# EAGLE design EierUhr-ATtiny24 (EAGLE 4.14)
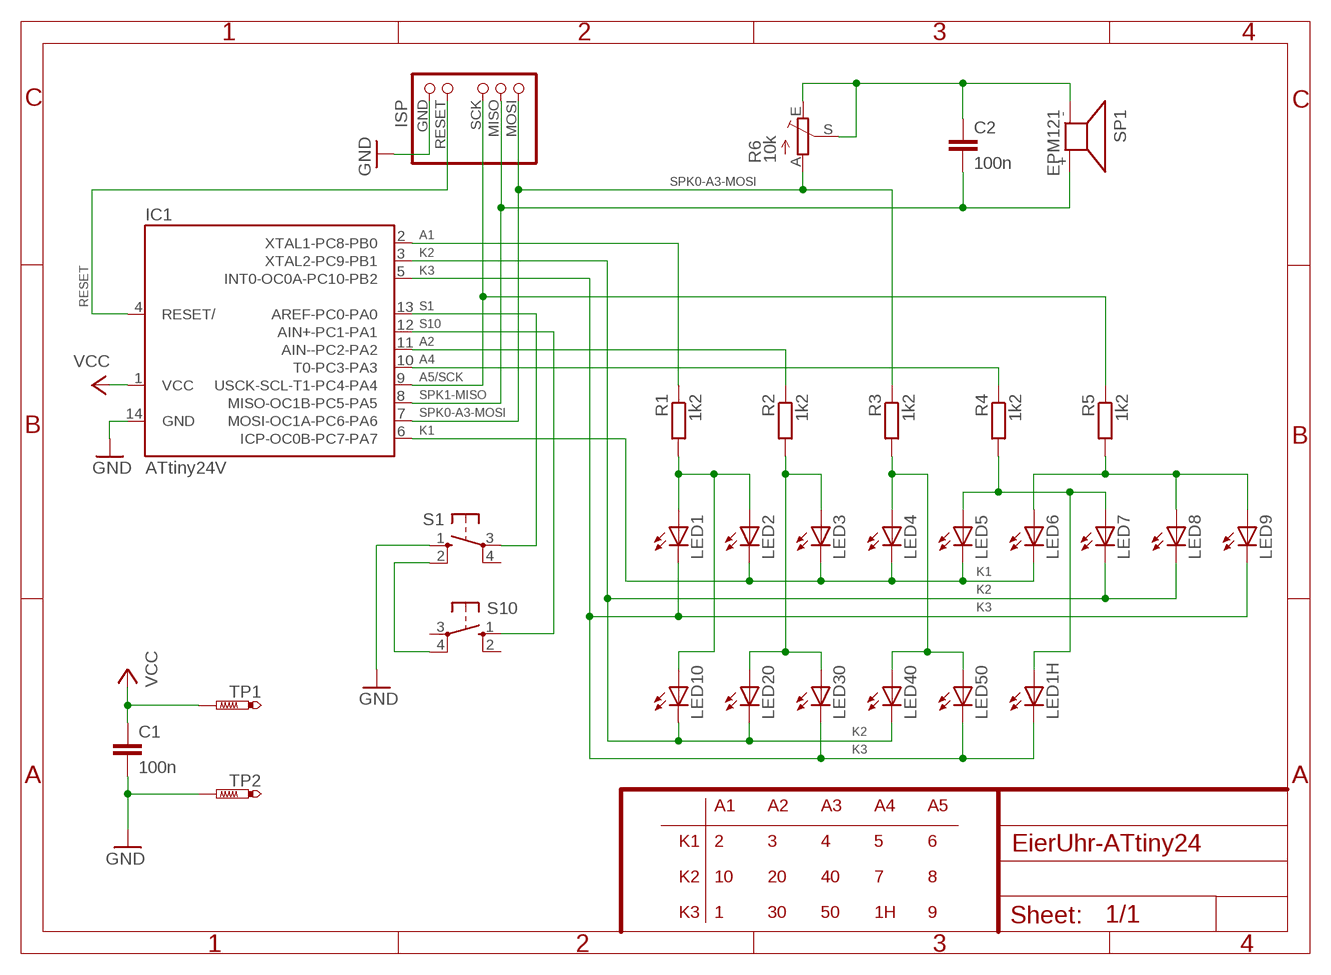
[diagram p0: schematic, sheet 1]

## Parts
C1  100n  C-EU050-024X044  [C050-024X044]
C2  100n  C-EU050-024X044  [C050-024X044]
IC1  ATtiny24V  ATTINY24P  [DIL14]
ISP  ISP-2  [PINHD6.ISP-2]
LED1  LED3MM  [LED3MM]
LED1H  LED3MM  [LED3MM]
LED2  LED3MM  [LED3MM]
LED3  LED3MM  [LED3MM]
LED4  LED3MM  [LED3MM]
LED5  LED3MM  [LED3MM]
LED6  LED3MM  [LED3MM]
LED7  LED3MM  [LED3MM]
LED8  LED3MM  [LED3MM]
LED9  LED3MM  [LED3MM]
LED10  LED3MM  [LED3MM]
LED20  LED3MM  [LED3MM]
LED30  LED3MM  [LED3MM]
LED40  LED3MM  [LED3MM]
LED50  LED3MM  [LED3MM]
R1  1k2  R-EU_0204/5  [0204/5]
R2  1k2  R-EU_0204/5  [0204/5]
R3  1k2  R-EU_0204/5  [0204/5]
R4  1k2  R-EU_0204/5  [0204/5]
R5  1k2  R-EU_0204/5  [0204/5]
R6  10k  TRIM_EU-S75H  [S75H]
S1  10-XX  [B3F-10XX]
S10  10-XX  [B3F-10XX]
SP1  EPM121  AL11P  [AL11P]
TP1  PTR1PAD1-13  [P1-13]
TP2  PTR1PAD1-13  [P1-13]

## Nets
A1: IC1.2(XTAL1-PC8-PB0) R1.1
A1.R: LED1.A LED2.A LED10.A R1.2
A2: IC1.11(AIN--PC2-PA2) R2.1
A2.R: LED3.A LED20.A LED30.A R2.2
A3.R: LED4.A LED40.A LED50.A R3.2
A4: IC1.10(T0-PC3-PA3) R4.1
A4.R: LED1H.A LED5.A LED7.A R4.2
A5.R: LED6.A LED8.A LED9.A R5.2
A5/SCK: IC1.9(USCK-SCL-T1-PC4-PA4) ISP.SCK R5.1
GND: C1.2 IC1.14(GND) ISP.GND S1.1(S) TP2.1(TP)
GND2: S1.2(S1) S10.4(P1)
K1: IC1.6(ICP-OC0B-PC7-PA7) LED2.K(C) LED3.K(C) LED4.K(C) LED5.K(C) LED6.K(C)
K2: IC1.3(XTAL2-PC9-PB1) LED7.K(C) LED8.K(C) LED10.K(C) LED20.K(C) LED40.K(C)
K3: IC1.5(INT0-OC0A-PC10-PB2) LED1.K(C) LED1H.K(C) LED9.K(C) LED30.K(C) LED50.K(C)
RESET: IC1.4(RESET/) ISP.RESET
S1: IC1.13(AREF-PC0-PA0) S1.3(P)
S10: IC1.12(AIN+-PC1-PA1) S10.1(S)
SPK: C2.1 R6.E R6.S SP1.-
SPK0-A3-MOSI: IC1.7(MOSI-OC1A-PC6-PA6) ISP.MOSI R3.1 R6.A
SPK1-MISO: C2.2 IC1.8(MISO-OC1B-PC5-PA5) ISP.MISO SP1.+
VCC: C1.1 IC1.1(VCC) TP1.1(TP)
Unconnected: S1.4(P1) S10.2(S1) S10.3(P)

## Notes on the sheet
- A1 | A2 | A3 | A4 | A5
- K1 | 2 | 3 | 4 | 5 | 6
- K2 | 10 | 20 | 40 | 7 | 8
- K3 | 1 | 30 | 50 | 1H | 9

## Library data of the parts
C1 C2 = rcl:C-EU: CAPACITOR, European symbol
IC1 = atmel-gjl:ATTINY24
ISP = eigene:ISP
LED1 LED1H LED2-LED10 LED20 LED30 LED40 LED50 = led:LED: LED
R1-R5 = rcl:R-EU_: RESISTOR, European symbol
R6 = pot:TRIM_EU-: POTENTIOMETER
S1 S10 = switch-omron:10-XX: OMRON SWITCH
SP1 = buzzer:AL11P: SPEAKER
TP1 TP2 = testpad:PTR1: TEST PIN

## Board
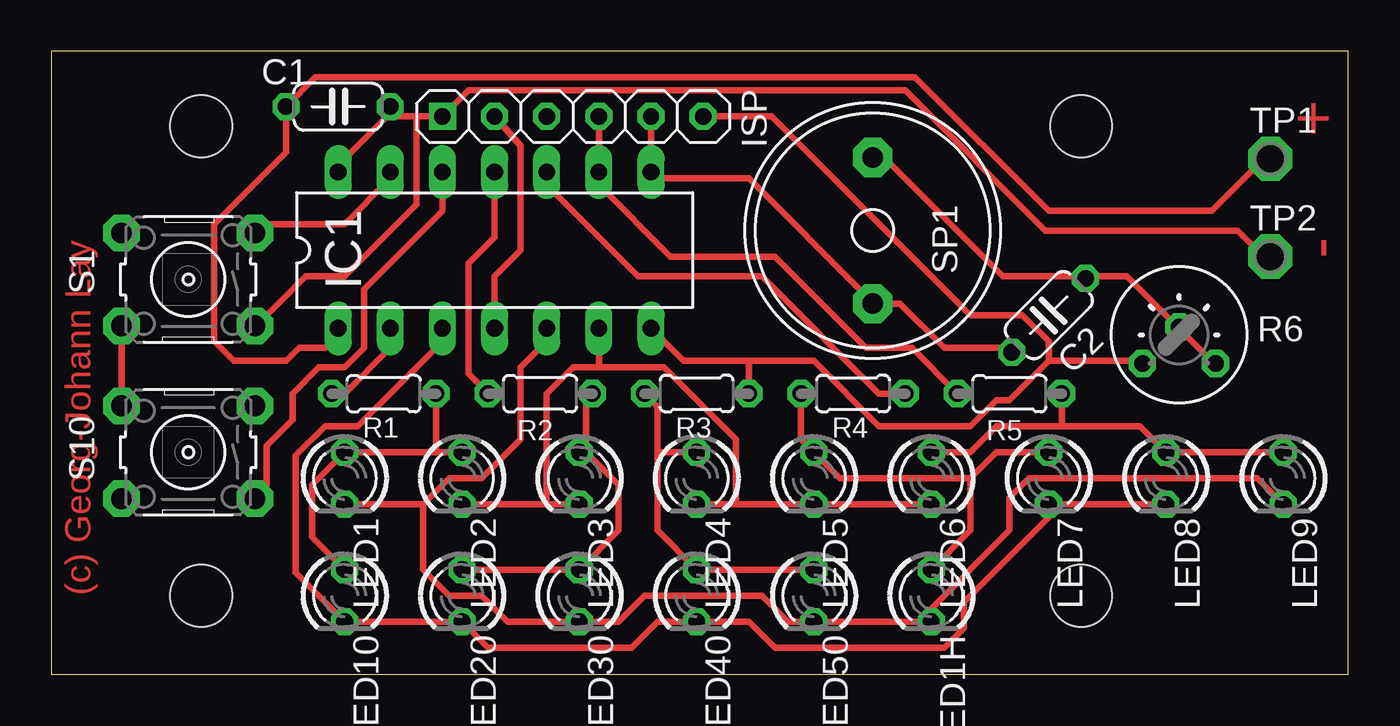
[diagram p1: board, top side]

Size 63.17 x 30.34 mm. Coordinates in mm from the lower left corner, seen from the top.
Outline: 0,0 63.17,0 63.17,30.34 0,30.34 0,0
Copper layers (1+16): Top 0.035mm / dielectric 1.5mm / Bottom 0.035mm
Design rules "default": minimum track width 10mil, minimum drill 23mil, track to track 8mil, track to pad 8mil, pad to pad 8mil, via to via 8mil, smd to smd 8mil, copper to edge 40mil, drill to drill 8mil, minimum pad ring 10mil, minimum via ring 8mil, stop-mask expansion 4mil, vias tented up to drill 0mil, thermal gap 10mil
vRestrict: area 55.7,0 to 63.2,30.3

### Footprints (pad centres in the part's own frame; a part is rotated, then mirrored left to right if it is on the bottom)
C050-024X044 = drill 0.813 octagon: 1 -2.54,0; 2 2.54,0
DIL14 = drill 0.813 long: 1 -7.62,-3.81; 2 -5.08,-3.81; 3 -2.54,-3.81; 4 0,-3.81; 5 2.54,-3.81; 6 5.08,-3.81; 7 7.62,-3.81; 8 7.62,3.81; 9 5.08,3.81; 10 2.54,3.81; 11 0,3.81; 12 -2.54,3.81; 13 -5.08,3.81; 14 -7.62,3.81
PINHD6.ISP-2 = drill 0.8 square: GND -6.35,0 | drill 0.8 octagon: MISO 3.81,0; MOSI 6.35,0; P$1 -1.27,0; RESET -3.81,0; SCK 1.27,0
LED3MM = drill 0.813 octagon: A -1.27,0; K 1.27,0
0204/5 = drill 0.813 octagon: 1 -2.54,0; 2 2.54,0
S75H = drill 0.813 octagon: A -1.778,-1.397; E 1.778,-1.397; S 0,0.381
B3F-10XX = drill 1.016 pad 1.778 octagon: 1 -3.251,2.261; 2 3.251,2.261; 3 -3.251,-2.261; 4 3.251,-2.261
AL11P = drill 1.016 pad 1.905 octagon: + 3.556,0; - -3.556,0
P1-13 = drill 1.321 pad 2.159 octagon: 1 0,0
BOHRUNG_3MM = hole 3: 0,0

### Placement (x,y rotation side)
C1  13.97,27.64 0 top
C2  48.58,17.48 225 top
IC1  21.59,20.66 0 top
ISP  25.4,27.17 0 top
LED1  14.29,9.55 270 top
LED1H  42.86,3.83 270 top
LED2  20,9.55 270 top
LED3  25.72,9.55 270 top
LED4  31.43,9.55 270 top
LED5  37.15,9.55 270 top
LED6  42.86,9.55 270 top
LED7  48.58,9.55 270 top
LED8  54.29,9.55 270 top
LED9  60.01,9.55 270 top
LED10  14.29,3.83 270 top
LED20  20,3.83 270 top
LED30  25.72,3.83 270 top
LED40  31.43,3.83 270 top
LED50  37.15,3.83 270 top
R1  16.19,13.67 0 top
R2  23.81,13.67 0 top
R3  31.43,13.67 180 top
R4  39.05,13.67 180 top
R5  46.67,13.67 0 top
R6  54.93,16.53 0 top
S1  6.67,19.23 180 top
S10  6.67,10.82 180 top
SP1  40.01,21.61 270 top
TP1  59.37,25.1 0 top
TP2  59.37,20.34 0 top
U$5  [BOHRUNG_3MM]  50.17,3.83 0 top
U$6  [BOHRUNG_3MM]  50.17,26.69 0 top
U$7  [BOHRUNG_3MM]  7.3,26.69 0 top
U$8  [BOHRUNG_3MM]  7.3,3.83 0 top

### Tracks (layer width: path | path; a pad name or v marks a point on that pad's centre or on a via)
A1
  Top 0.305: R1.1 14.29,13.67 16.51,15.9 IC1.2
A1.R
  Top 0.305: LED10.A 12.7,6.69 12.7,9.23 LED1.A LED2.A 18.73,10.82 R1.2
A2
  Top 0.305: IC1.11 21.59,21.29 20.32,20.02 20.32,14.63 R2.1
A2.R
  Top 0.305: LED20.A LED30.A 27.62,7.01 27.62,9.23 26.04,10.82 | 26.04,10.82 26.04,13.36 R2.2 | 26.04,10.82 LED3.A
A3.R
  Top 0.305: LED50.A LED40.A 29.53,7.01 29.53,10.82 | 29.53,10.82 LED4.A | 29.53,10.82 29.53,13.04 R3.2
A4
  Top 0.305: IC1.10 24.13,23.83 28.58,19.39 34.61,19.39 40.32,13.67 R4.1
A4.R
  Top 0.305: LED7.A 46.04,10.82 44.77,9.55 | 44.77,9.55 38.42,9.55 LED5.A 36.51,11.45 R4.2 | 44.77,9.55 44.77,7.01 LED1H.A
A5.R
  Top 0.305: LED9.A LED8.A 53.02,12.09 49.21,12.09 | LED6.A 44.77,10.82 46.04,12.09 49.21,12.09 | 49.21,12.09 R5.2
A5/SCK
  Top 0.254: IC1.9 26.67,23.83
  Top 0.305: IC1.9 ISP.SCK | 26.67,23.83 30.16,20.34 35.24,20.34 39.69,15.9 41.91,15.9 R5.1
GND
  Top 0.254: 13.97,24.79 IC1.14
  Top 0.305: S1.1 9.92,16.92 12.38,19.39 14.29,19.39 17.78,22.88 17.78,27.17 | TP2.1 59.06,20.34 57.79,21.61 48.42,21.61 41.59,28.44 20.32,28.44 ISP.GND 17.78,27.17 | 17.78,27.17 16.35,27.17 | 16.35,27.17 13.97,24.79 | 16.35,27.17 C1.2
GND2
  Top 0.254: 3.42,16.61 S1.2 | 3.42,16.45 3.49,16.53
  Top 0.305: 3.49,16.53 3.42,16.61 | S10.4 3.42,16.45
K1
  Top 0.305: 33.34,8.28 LED5.K LED6.K | 24.13,8.28 LED3.K | 24.13,8.28 24.13,13.67 25.4,14.94 26.67,14.94 | 33.34,8.28 LED4.K | 33.34,8.28 33.34,11.45 29.85,14.94 26.67,14.94 | LED2.K 24.13,8.28 | 26.67,14.94 IC1.6
K2
  Top 0.305: LED8.K LED7.K 48.58,7.64 44.45,3.51 44.45,2.24 43.5,1.29 35.24,1.29 33.97,2.56 LED40.K 29.53,2.56 28.26,1.29 21.27,1.29 LED20.K LED10.K 11.91,4.94 11.91,10.66 13.34,12.09 14.92,12.09 19.05,16.21 IC1.3
K3
  Top 0.305: LED9.K 58.74,9.55 47.63,9.55 46.67,8.59 46.67,7.01 42.86,3.2 LED1H.K LED50.K 35.88,2.56 34.61,3.83 28.89,3.83 27.62,2.56 LED30.K 22.23,2.56 20.96,3.83 19.37,3.83 18.1,5.1 18.1,8.28 | IC1.5 24.13,16.21 22.86,14.94 22.86,11.45 20.96,9.55 19.37,9.55 18.1,8.28 | LED1.K 18.1,8.28
RESET
  Top 0.305: ISP.RESET 22.86,25.74 22.86,20.66 21.59,19.39 IC1.4
S1
  Top 0.254: S1.3 9.92,21.37
  Top 0.305: IC1.13 16.51,24.15 14.29,21.93 10.48,21.93 9.92,21.37
S10
  Top 0.305: IC1.12 19.05,22.56 15.24,18.75 15.24,15.9 14.29,14.94 13.02,14.94 11.75,13.67 11.75,12.4 10.48,11.13 10.48,9.23 9.84,8.59 9.88,8.55 S10.1
SPK
  Top 0.254: SP1.- 40.64,25.1
  Top 0.305: 40.64,25.1 46.36,19.39 50.48,19.39 | 50.48,19.39 52.39,19.39 54.93,16.85 | 54.93,16.85 R6.S | R6.E 56.64,15.13 54.93,16.85 | 50.48,19.39 C2.1
SPK0-A3-MOSI
  Top 0.305: ISP.MOSI 31.91,27.17 35.08,27.17 44.77,17.48 47.31,17.48 48.58,16.21 48.58,15.26 | 33.97,15.26 37.15,15.26 40.32,12.09 44.77,12.09 46.04,13.36 46.67,13.36 48.58,15.26 | IC1.7 30.8,15.26 33.97,15.26 | 33.97,15.26 R3.1 | R6.A 53.02,15.26 48.58,15.26
SPK1-MISO
  Top 0.254: 39.69,18.44 SP1.+
  Top 0.305: 39.69,18.44 33.97,24.15 29.21,24.15 IC1.8 ISP.MISO | SP1.+ 41.34,18.05 43.5,15.9 46.67,15.9 C2.2
VCC
  Top 0.305: IC1.1 13.97,16.53 13.34,15.9 12.07,15.9 11.43,15.26 8.89,15.26 7.94,16.21 7.94,21.93 11.43,25.42 C1.1 12.86,29.07 42.07,29.07 48.58,22.56 56.52,22.56 59.06,25.1 TP1.1

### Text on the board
Top: + | - | (c) Georg-Johann Lay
